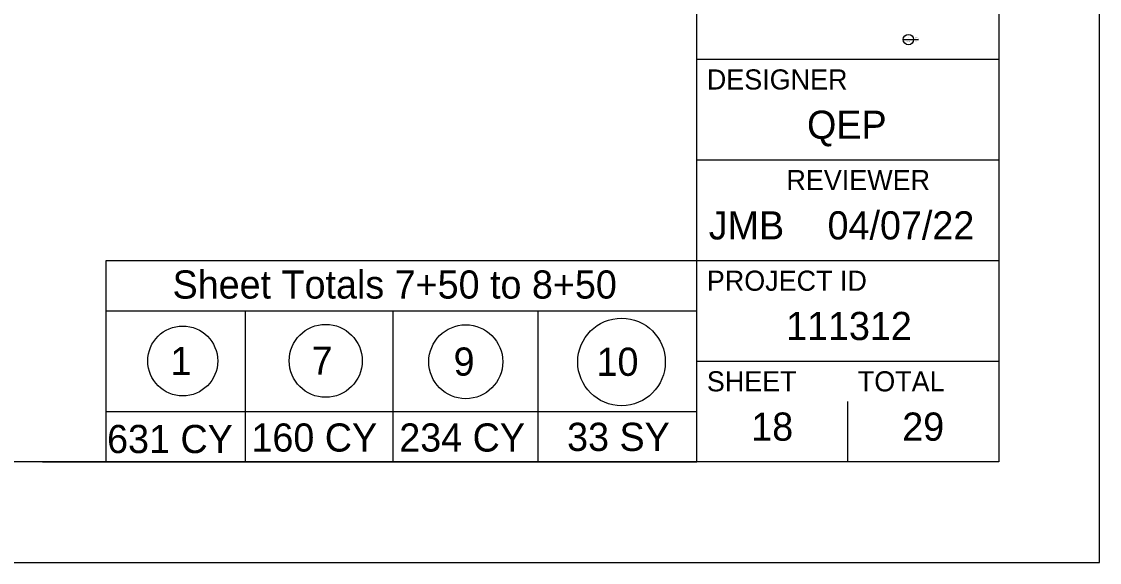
# Model space of a CAD drawing. Extents: x -31.8 to 34, y 0 to 22.
# Drawn here: x 28.65 to 34, y 0 to 2.69 of the extents above; entities that cross this region are included whole.
import ezdxf

# ---------------------------------------------------------------- set-up
doc = ezdxf.new("R2010")
doc.units = 0
for name, color, linetype in [('CS-ALGN-TEXT', 7, 'Continuous'), ('CS-ANNO', 7, 'Continuous'), ('CS-ANNO-MATC', 7, 'Continuous'), ('CS-ANNO-MATC-TEXT', 7, 'Continuous'), ('CS-ANNO-TABL', 7, 'Continuous')]:
    doc.layers.add(name, color=color, linetype=linetype)

msp = doc.modelspace()

# ---------------------------------------------------------------- linework, layer by layer
at = {"layer": 'CS-ALGN-TEXT'}
for p, q in [((29.066, 0.5), (29.066, 1.5)), ((29.066, 1.5), (32, 1.5)), ((29.066, 1.25), (32, 1.25)), ((29.7592, 0.5), (29.7592, 1.25)), ((30.4922, 0.5), (30.4922, 1.25)), ((31.2115, 0.5), (31.2115, 1.25)), ((29.066, 0.75), (32, 0.75)), ((32.75, 0.5), (32.75, 0.8)), ((32.375, 0.675), (32.375, 0.675)), ((28.75, 0.5), (32, 0.5))]:
    msp.add_line(p, q, dxfattribs=at)
at = {"layer": 'CS-ANNO'}
msp.add_lwpolyline([(0, 0), (34, 0), (34, 22), (0, 22)], close=True, dxfattribs=at)
at = {"layer": 'CS-ANNO-MATC'}
for p, q in [((32, 0.5), (32, 21.5)), ((32, 2.5), (33.5, 2.5)), ((32, 2), (33.5, 2)), ((32, 1.5), (33.5, 1.5)), ((32, 1), (33.5, 1))]:
    msp.add_line(p, q, dxfattribs=at)
msp.add_lwpolyline([(1.5, 21.5), (33.5, 21.5), (33.5, 0.5), (1.5, 0.5)], close=True, dxfattribs=at)
at = {"layer": 'CS-ANNO-MATC-TEXT'}
for centre, radius in [((30.157, 1.0018), 0.1813), ((30.8527, 0.9973), 0.1837), ((31.6263, 0.9963), 0.2175), ((29.4469, 1.0012), 0.1737)]:
    msp.add_circle(centre, radius, dxfattribs=at)
at = {"layer": 'CS-ANNO-TABL'}
for p, q in [((33.0249, 2.5979), (33.077, 2.5979)), ((33.0512, 2.5979), (33.1007, 2.5979))]:
    msp.add_line(p, q, dxfattribs=at)
msp.add_circle((33.051, 2.5979), 0.026, dxfattribs=at)

# ---------------------------------------------------------------- texts
at = {"layer": 'CS-ALGN-TEXT'}
for s, height, p in [('DESIGNER', 0.1, (32.05, 2.35)), ('QEP', 0.14, (32.5477, 2.105)), ('REVIEWER', 0.1, (32.4454, 1.85)), ('JMB', 0.14, (32.0596, 1.605)), ('04/07/22', 0.14, (32.6497, 1.605)), ('Sheet Totals 7+50 to 8+50', 0.14, (29.3964, 1.3111)), ('PROJECT ID', 0.1, (32.05, 1.35)), ('111312', 0.14, (32.4435, 1.105)), ('SHEET', 0.1, (32.05, 0.85)), ('TOTAL', 0.1, (32.8, 0.85)), ('18', 0.14, (32.2706, 0.605)), ('29', 0.14, (33.0206, 0.605))]:
    msp.add_text(s, height=height, dxfattribs=at).set_placement(p)
at = {"layer": 'CS-ANNO-MATC-TEXT'}
for s, p in [('1', (29.3856, 0.931)), ('7', (30.0869, 0.9328)), ('9', (30.7922, 0.9282)), ('10', (31.5023, 0.9272)), ('33 SY', (31.3559, 0.5541)), ('631 CY', (29.0712, 0.5434)), ('160 CY', (29.7881, 0.5508)), ('234 CY', (30.5224, 0.5509))]:
    msp.add_text(s, height=0.14, dxfattribs=at).set_placement(p)
at = {"layer": 'CS-ANNO-TABL'}
for s, p in [('8+00.00', (33.043, 2.5881)), ('2', (33.0498, 2.6045)), ('Drawing', (33.0838, 2.6045)), ('1:2', (33.0838, 2.5881))]:
    msp.add_text(s, height=0.00328, dxfattribs=at).set_placement(p)

doc.saveas('drawing.dxf')
